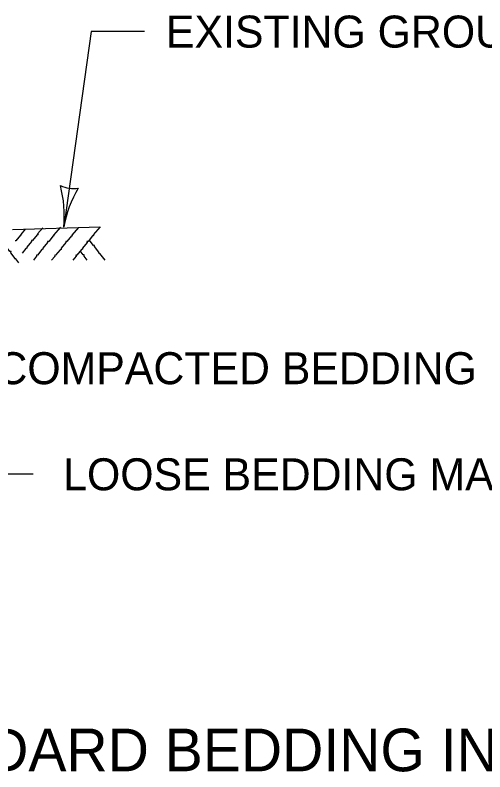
# Model space of a CAD drawing. Extents: x 49991.4 to 50021, y 49987.6 to 50011.4.
# Drawn here: x 50005.577 to 50006.457, y 49995.675 to 49997.094 of the extents above; entities that cross this region are included whole.
import ezdxf

# ---------------------------------------------------------------- set-up
doc = ezdxf.new("R2010")
doc.units = 0
for name, color, linetype in [('Level 1', 7, 'Continuous'), ('Level 2', 7, 'Continuous'), ('Level 3', 7, 'Continuous')]:
    doc.layers.add(name, color=color, linetype=linetype)

msp = doc.modelspace()

# ---------------------------------------------------------------- linework, layer by layer
at = {"layer": 'Level 1'}
msp.add_line((50005.5724, 49996.6918), (50005.7362, 49996.6967), dxfattribs=at)
for points in [[(50005.5838, 49996.6292), (50005.5785, 49996.6365), (50005.5768, 49996.6361), (50005.5772, 49996.6376), (50005.5689, 49996.6483), (50005.5694, 49996.6503), (50005.5674, 49996.6506), (50005.559, 49996.6615), (50005.5571, 49996.662), (50005.5569, 49996.664), (50005.5486, 49996.6745), (50005.5489, 49996.6765), (50005.5469, 49996.6766), (50005.5374, 49996.6892)], [(50005.5959, 49996.6923), (50005.5877, 49996.6827), (50005.5885, 49996.6811), (50005.5869, 49996.6811), (50005.5784, 49996.6706), (50005.5773, 49996.6707)], [(50005.6291, 49996.695), (50005.6191, 49996.6834), (50005.6199, 49996.6818), (50005.6183, 49996.6818), (50005.6098, 49996.6713), (50005.6077, 49996.6714), (50005.6079, 49996.6693), (50005.5991, 49996.6588), (50005.5991, 49996.6567), (50005.5972, 49996.6561), (50005.5903, 49996.6474)], [(50005.6619, 49996.6962), (50005.6492, 49996.6814), (50005.65, 49996.6798), (50005.6484, 49996.6798), (50005.6399, 49996.6694), (50005.6377, 49996.6694), (50005.638, 49996.6674), (50005.6292, 49996.6568), (50005.6292, 49996.6547), (50005.6273, 49996.6541), (50005.6189, 49996.6436), (50005.6169, 49996.6435), (50005.6173, 49996.6415), (50005.6112, 49996.6344)], [(50005.6956, 49996.6956), (50005.6833, 49996.6811), (50005.684, 49996.6795), (50005.6824, 49996.6796), (50005.6739, 49996.6691), (50005.6718, 49996.6691), (50005.672, 49996.6671), (50005.6632, 49996.6565), (50005.6632, 49996.6545), (50005.6613, 49996.6538), (50005.653, 49996.6434), (50005.651, 49996.6432), (50005.6513, 49996.6412), (50005.6453, 49996.6341)], [(50005.7362, 49996.6967), (50005.7232, 49996.6816), (50005.7239, 49996.6799), (50005.7223, 49996.68), (50005.7138, 49996.6695), (50005.7117, 49996.6695), (50005.7119, 49996.6675), (50005.7032, 49996.6569), (50005.7031, 49996.6549), (50005.7012, 49996.6542), (50005.6929, 49996.6438), (50005.6908, 49996.6437), (50005.6912, 49996.6416), (50005.6852, 49996.6345)], [(50005.7455, 49996.6345), (50005.736, 49996.6469), (50005.7341, 49996.6474), (50005.7339, 49996.6493), (50005.7255, 49996.6599), (50005.7259, 49996.6618), (50005.7238, 49996.6619), (50005.716, 49996.6724)], [(50005.7122, 49996.6345), (50005.7063, 49996.642), (50005.7067, 49996.644), (50005.7046, 49996.6441), (50005.6989, 49996.6517)]]:
    msp.add_lwpolyline(points, dxfattribs=at)
at = {"layer": 'Level 3'}
for p, q in [((50005.7193, 49997.0628), (50005.6682, 49996.6965)), ((50005.8193, 49997.0628), (50005.7193, 49997.0628)), ((50005.611, 49996.2328), (50004.0966, 49996.2328))]:
    msp.add_line(p, q, dxfattribs=at)
for centre, radius, start, end in [((50005.6859, 49996.8234), 0.0548, 244.1946, 279.917), ((50005.4361, 49996.7172), 0.233, 354.8831, 14.1329), ((50005.8869, 49996.6567), 0.2223, 149.5118, 169.6953)]:
    msp.add_arc(centre, radius, start, end, dxfattribs=at)

# ---------------------------------------------------------------- texts
at = {"layer": 'Level 2'}
for s, height, p in [('EXISTING GROUND', 0.06, (50005.8597, 49997.0328)), ('COMPACTED BEDDING MATERIAL', 0.06, (50005.542, 49996.4017)), ('LOOSE BEDDING MATERIAL', 0.06, (50005.6671, 49996.2028)), ('1-STANDARD BEDDING INSTALLATION', 0.08, (50005.1442, 49995.676))]:
    msp.add_text(s, height=height, dxfattribs=at).set_placement(p)

doc.saveas('drawing.dxf')
